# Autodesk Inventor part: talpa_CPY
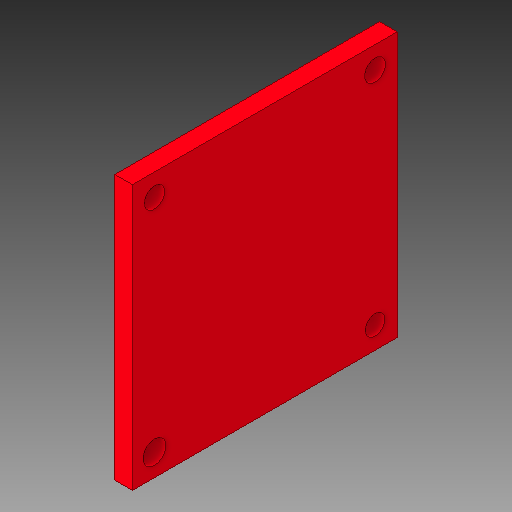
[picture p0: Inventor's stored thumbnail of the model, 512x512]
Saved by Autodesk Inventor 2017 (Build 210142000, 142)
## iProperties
Created: 2017-11
Part Number: talpa_CPY
Material: Generic
Document SubType Name: Modeling
Designer: iusti
Mass: 1764.05 g
Surface Area: 2064.07 cm^2
Volume: 1764.05 cm^3
Density: 1 g/cm^3
Appearance: Default
Author: iusti
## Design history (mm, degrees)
sketch "Sketch1"
  geometry: L1 (150, 150)-(-150, 150); L2 (-150, 150)-(-150, -150); L3 (-150, -150)-(150, -150); L4 (150, -150)-(150, 150); C1 r 11.55 at (125, 125); C2 r 11.969 at (125, -125); C3 r 11.188 at (-125, -125); C4 r 13.05 at (-125, 125); 1 further point
  constraints: 8 end point, 4 centre point, 2 parallel, 1 horizontal, 1 perpendicular
  dimensions: "d0" = 300 distance of L3.end L1.start; "d1" = 300 distance of L2.end L3.end; "d2" = 250 distance of C2.centre C1.centre; "d3" = 250 distance of C4.centre C1.centre; "d4" = 250 distance of C3.centre C2.centre (= d3); "d5" = 250 distance of C3.centre C4.centre (= d2); "d6" = 25 distance from line of L1 C1.centre; "d7" = 25 distance from line of L4 C1.centre; "d8" = 25 distance from line of L3 C3.centre; "d9" = 25 distance from line of L2 C3.centre
extrude "Extrusion1" new body sketch "Sketch1" distance "d10" = 20; taper "d11" = 0 deg
body "Solid1"
